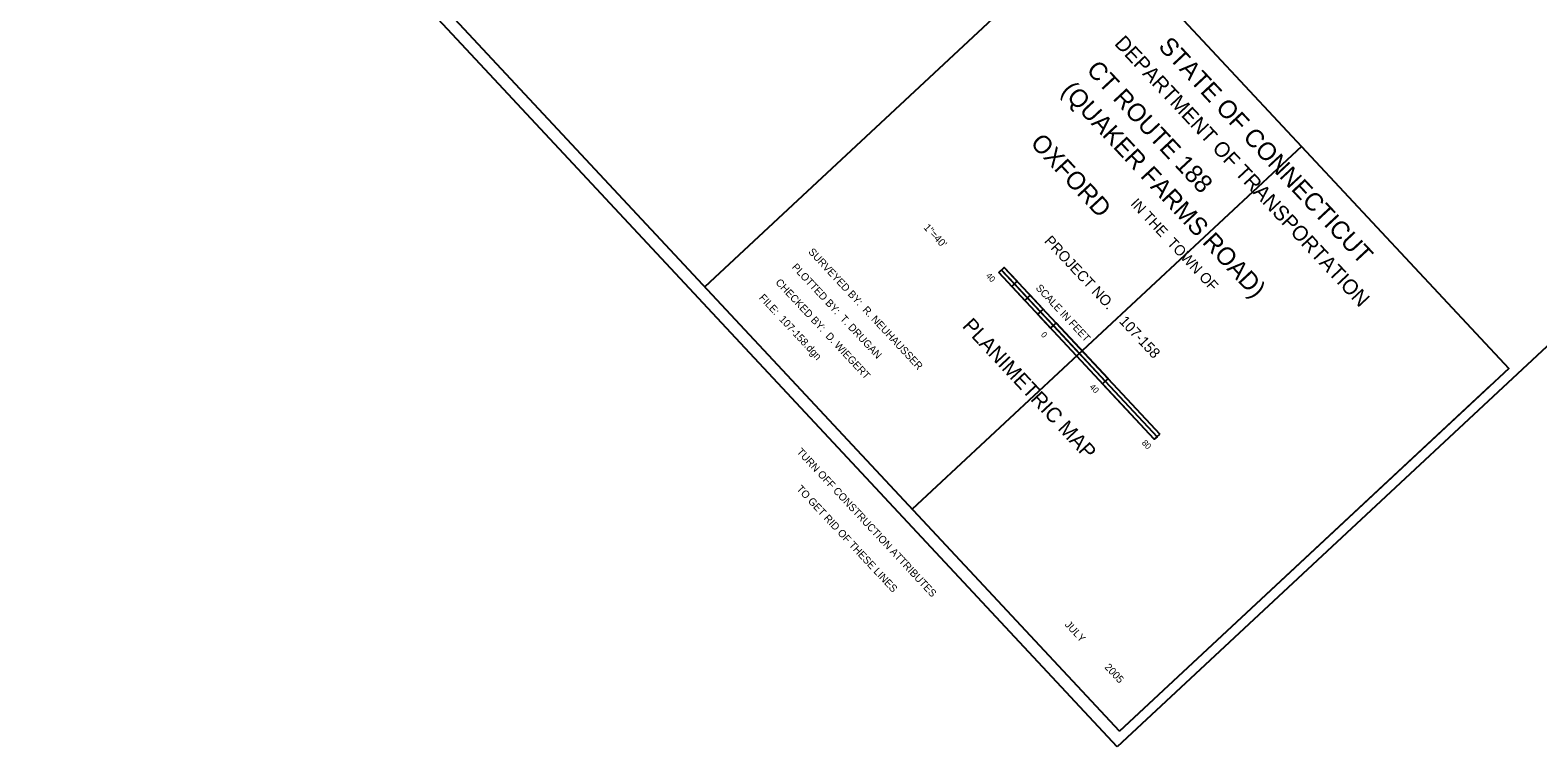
# Model space of a CAD drawing. Extents: x 487096 to 489566, y 221939 to 224454.
# Drawn here: x 488036 to 488829, y 221939 to 222316 of the extents above; entities that cross this region are included whole.
import ezdxf

# ---------------------------------------------------------------- set-up
doc = ezdxf.new("R2010")
doc.units = 0
for name, color, linetype in [('SV_MAPI_BORDERS', 7, 'Continuous'), ('SV_MAPI_BSFEET', 7, 'Continuous'), ('SV_MAPI_NOTE', 7, 'Continuous')]:
    doc.layers.add(name, color=color, linetype=linetype)

msp = doc.modelspace()

# ---------------------------------------------------------------- linework, layer by layer
at = {"layer": 'SV_MAPI_BORDERS'}
for p, q in [((488595.77, 222371.97), (488390.99, 222181.01)), ((488704.89, 222254.95), (488500.11, 222063.99)), ((488609.23, 221946.97), (488804.98, 222129.52))]:
    msp.add_line(p, q, dxfattribs=at)
for points in [[(488607.95, 221938.76), (487095.64, 223560.51), (488053.67, 224453.88), (489565.97, 222832.14)], [(488609.23, 221946.97), (488227.31, 222356.53), (488432.09, 222547.49), (488814.01, 222137.93)]]:
    msp.add_lwpolyline(points, close=True, dxfattribs=at)
at = {"layer": 'SV_MAPI_BSFEET'}
for p, q in [((488627.47, 222100.71), (488545.64, 222188.48)), ((488545.65, 222188.49), (488548.56, 222191.21)), ((488547.1, 222189.85), (488628.94, 222102.09)), ((488548.56, 222191.21), (488630.4, 222103.44)), ((488552.46, 222181.17), (488555.37, 222183.89)), ((488559.28, 222173.85), (488562.2, 222176.58)), ((488566.1, 222166.54), (488569.02, 222169.26)), ((488572.92, 222159.23), (488575.84, 222161.95)), ((488600.19, 222129.97), (488603.12, 222132.7)), ((488627.47, 222100.71), (488630.4, 222103.44))]:
    msp.add_line(p, q, dxfattribs=at)
for points in [[(488547.1, 222189.85), (488553.92, 222182.53), (488555.37, 222183.89), (488548.55, 222191.2)], [(488560.74, 222175.22), (488553.92, 222182.53), (488552.46, 222181.17), (488559.28, 222173.86)], [(488560.74, 222175.22), (488567.56, 222167.9), (488569.02, 222169.26), (488562.2, 222176.58)], [(488574.38, 222160.59), (488567.56, 222167.9), (488566.1, 222166.54), (488572.92, 222159.23)], [(488574.38, 222160.59), (488601.65, 222131.34), (488603.12, 222132.7), (488575.84, 222161.95)], [(488601.65, 222131.34), (488628.93, 222102.08), (488627.47, 222100.71), (488600.19, 222129.97)]]:
    msp.add_lwpolyline(points, close=True, dxfattribs=at)
at = {"layer": 'SV_MAPI_NOTE'}
msp.add_line((488390.99, 222181.01), (488390.99, 222181.01), dxfattribs=at)

# ---------------------------------------------------------------- texts
at = {"layer": 'SV_MAPI_BORDERS'}
for s, height, rotation, p in [('DEPARTMENT OF TRANSPORTATION', 7.874, 313.00011, (488606.08, 222308.78)), ('STATE OF CONNECTICUT', 9.4488, 312.99987, (488629.17, 222307.16)), ('         CT ROUTE 188         ', 9.4488, 313, (488569.77, 222317.87)), ('      (QUAKER FARMS ROAD)     ', 9.4488, 313, (488563.73, 222299.15)), ('            OXFORD            ', 9.4488, 313, (488533.12, 222287.09)), ('IN THE  TOWN OF', 5.5118, 313, (488614.62, 222224.42)), ('PROJECT NO.    107-158  ', 5.5118, 313, (488569.26, 222204.81)), ('TURN OFF CONSTRUCTION ATTRIBUTES', 3.937, 313, (488439.02, 222093.85)), ('TO GET RID OF THESE LINES', 3.937, 313, (488438.94, 222074.31)), ('    JULY   ', 3.937, 313, (488576.11, 222007.19)), ('2005', 3.937, 313, (488601.03, 221980.48))]:
    msp.add_text(s, height=height, rotation=rotation, dxfattribs=at).set_placement(p)
at = {"layer": 'SV_MAPI_BSFEET'}
for s, height, rotation, p in [(' 40', 3.2, 313, (488537.79, 222187.47)), ('        SCALE IN FEET       ', 3.937, 313, (488556.82, 222188.69)), ('0', 3.2, 313.00008, (488567.56, 222155.55)), (' 40', 3.2, 313, (488592.34, 222128.95)), (' 80', 3.2, 313, (488619.84, 222099.49))]:
    msp.add_text(s, height=height, rotation=rotation, dxfattribs=at).set_placement(p)
at = {"layer": 'SV_MAPI_NOTE'}
for s, height, p in [('1"=40\'', 3.937, (488505.81, 222211.99)), ('SURVEYED BY:  R. NEUHAUSSER       ', 3.937, (488445.14, 222199.17)), ('PLOTTED BY:  T. DRUGAN           ', 3.937, (488436.5, 222191.11)), ('CHECKED BY:  D. WIEGERT          ', 3.937, (488427.86, 222183.06)), ('FILE:  107-158.dgn   ', 3.937, (488419.23, 222175)), ('PLANIMETRIC MAP', 7.874, (488526.02, 222160.01))]:
    msp.add_text(s, height=height, rotation=313, dxfattribs=at).set_placement(p)

doc.saveas('drawing.dxf')
